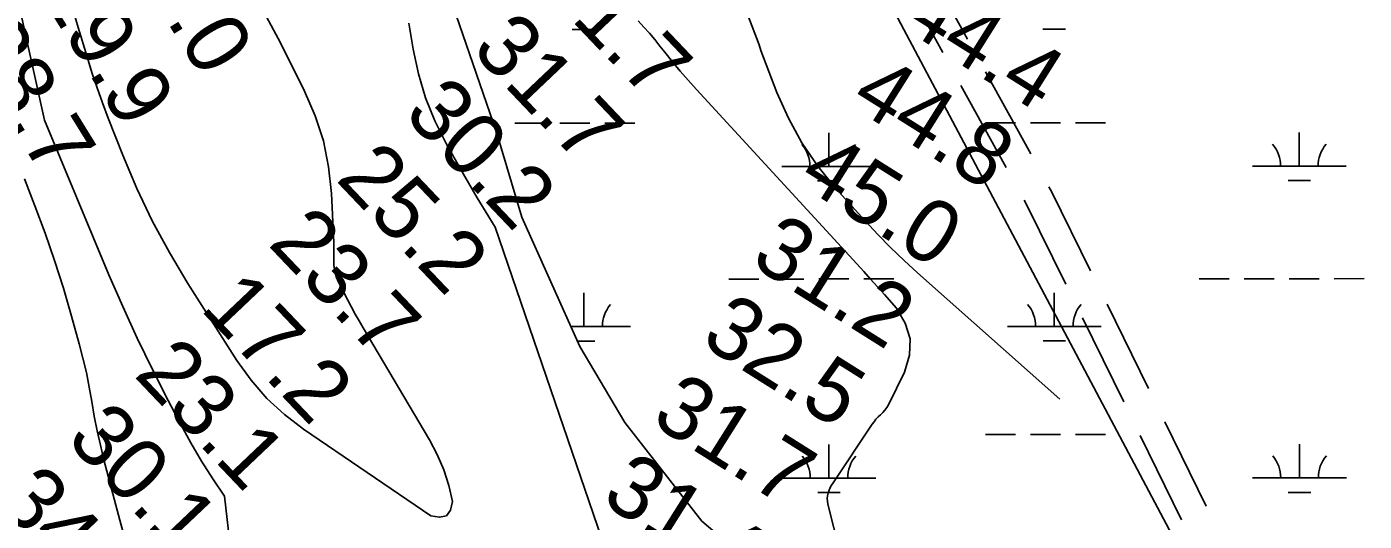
# Model space of a CAD drawing. Extents: x 3279314 to 3317160, y 734079 to 759431.
# Drawn here: x 3288596 to 3290023, y 756091 to 756619 of the extents above; entities that cross this region are included whole.
import ezdxf

# ---------------------------------------------------------------- set-up
doc = ezdxf.new("R2010")
doc.units = 0
for name, color, linetype in [('V-RIVR-RANG', 7, 'Continuous'), ('V-ROAD-CNTR', 7, 'Continuous'), ('V-SITE-VEGE', 7, 'Continuous'), ('V-TOPO-MAJR', 7, 'Continuous'), ('V-TOPO-MINR', 7, 'Continuous'), ('V-TOPO-SHOR', 7, 'Continuous'), ('V-WETL-SWMP', 7, 'Continuous')]:
    doc.layers.add(name, color=color, linetype=linetype)

msp = doc.modelspace()

# ---------------------------------------------------------------- linework, layer by layer
at = {"layer": 'V-ROAD-CNTR'}
for p, q in [((3289551.6, 756693.1), (3289599.8, 756605.5)), ((3289525.3, 756678.6), (3289573.5, 756591)), ((3289619.1, 756570.5), (3289667.3, 756482.9)), ((3289592.8, 756556), (3289641, 756468.4)), ((3289748.6, 756322.3), (3289792.7, 756232.6)), ((3289722.3, 756307.8), (3289766.4, 756218.1)), ((3289810.3, 756196.7), (3289854.5, 756106.9)), ((3289784, 756182.2), (3289828.2, 756092.4))]:
    msp.add_line(p, q, dxfattribs=at)
for points in [[(3289686.6, 756447.8), (3289689.4, 756442.7), (3289730.9, 756358.2)], [(3289660.3, 756433.3), (3289662.8, 756428.8), (3289704.6, 756343.7)]]:
    msp.add_lwpolyline(points, dxfattribs=at)
at = {"layer": 'V-SITE-VEGE'}
for p, q in [((3289388, 756887.4), (3289693.9, 756309.9)), ((3289097.3, 756506), (3289054.6, 756630.8)), ((3289124.5, 756415.2), (3289097.3, 756506)), ((3289186.3, 756277.4), (3289124.5, 756415.2)), ((3289693.9, 756309.9), (3289867.7, 755982.9)), ((3289234.3, 756196.2), (3289186.3, 756277.4)), ((3289316.6, 756090.7), (3289234.3, 756196.2))]:
    msp.add_line(p, q, dxfattribs=at)
at = {"layer": 'V-TOPO-MAJR'}
for p, q in [((3288585.8, 756653.3), (3288615.2, 756518.7)), ((3289008.5, 756594.8), (3289004, 756622.5)), ((3289014.1, 756568.4), (3289008.5, 756594.8)), ((3289021.6, 756542.7), (3289014.1, 756568.4)), ((3289031.8, 756518), (3289021.6, 756542.7)), ((3288615.2, 756518.7), (3288684.1, 756353.7)), ((3289043.8, 756493.8), (3289031.8, 756518)), ((3289058.3, 756468.1), (3289043.8, 756493.8)), ((3289067.5, 756452), (3289058.3, 756468.1)), ((3289076.9, 756436.1), (3289067.5, 756452)), ((3289086.4, 756420.2), (3289076.9, 756436.1)), ((3289096.1, 756404.5), (3289086.4, 756420.2)), ((3289238.2, 755988.5), (3289096.1, 756404.5)), ((3288684.1, 756353.7), (3288698.8, 756319.8)), ((3288698.8, 756319.8), (3288714.2, 756286.1)), ((3288714.2, 756286.1), (3288730.4, 756252.8)), ((3288730.4, 756252.8), (3288747.2, 756219.8)), ((3288747.2, 756219.8), (3288760.8, 756193.9)), ((3288760.8, 756193.9), (3288771.6, 756174.3)), ((3288771.6, 756174.3), (3288782.9, 756155)), ((3288782.9, 756155), (3288794.9, 756136.1)), ((3288794.9, 756136.1), (3288807.5, 756117.6)), ((3288807.5, 756117.6), (3288837.6, 755854.7))]:
    msp.add_line(p, q, dxfattribs=at)
at = {"layer": 'V-TOPO-MINR'}
for p, q in [((3289377.7, 756599.3), (3289100.2, 757319)), ((3289254.7, 756618.3), (3289248.7, 756624.9)), ((3289260.5, 756611.6), (3289254.7, 756618.3)), ((3289266.2, 756604.8), (3289260.5, 756611.6)), ((3289271.8, 756597.9), (3289266.2, 756604.8)), ((3289276.9, 756591.4), (3289271.8, 756597.9)), ((3289379.4, 756593.2), (3289377.7, 756599.3)), ((3289396.5, 756548.4), (3289379.4, 756593.2)), ((3289285.1, 756581.2), (3289276.9, 756591.4)), ((3289293.5, 756571.2), (3289285.1, 756581.2)), ((3289302, 756561.4), (3289293.5, 756571.2)), ((3289310.8, 756551.7), (3289302, 756561.4)), ((3289481.8, 756365.6), (3289310.8, 756551.7)), ((3289408.8, 756520.9), (3289396.5, 756548.4)), ((3289423, 756494.5), (3289408.8, 756520.9)), ((3289440.1, 756469.9), (3289423, 756494.5)), ((3289459, 756446.4), (3289440.1, 756469.9)), ((3289490.5, 756411.4), (3289459, 756446.4)), ((3289504, 756397), (3289490.5, 756411.4)), ((3289517.8, 756382.8), (3289504, 756397)), ((3289532.1, 756369.1), (3289517.8, 756382.8)), ((3289489.2, 756357.5), (3289481.8, 756365.6)), ((3289546.6, 756355.8), (3289532.1, 756369.1)), ((3289496.5, 756349.3), (3289489.2, 756357.5)), ((3289503.8, 756341.1), (3289496.5, 756349.3)), ((3289698.3, 756221), (3289546.6, 756355.8)), ((3289511.1, 756332.9), (3289503.8, 756341.1)), ((3289523.9, 756318.3), (3289511.1, 756332.9)), ((3289533.3, 756302.1), (3289523.9, 756318.3)), ((3289538.6, 756285.5), (3289533.3, 756302.1)), ((3289537.8, 756268), (3289538.6, 756285.5)), ((3289532.7, 756250), (3289537.8, 756268)), ((3289515.4, 756214.9), (3289532.7, 756250)), ((3289507.1, 756204.4), (3289509.6, 756206.7)), ((3289509.6, 756206.7), (3289511.8, 756209.2)), ((3289511.8, 756209.2), (3289513.7, 756212)), ((3289513.7, 756212), (3289515.4, 756214.9)), ((3289456.5, 756131.9), (3289498.1, 756194.3)), ((3289498.1, 756194.3), (3289500.1, 756197)), ((3289500.1, 756197), (3289502.2, 756199.7)), ((3289502.2, 756199.7), (3289504.6, 756202.1)), ((3289504.6, 756202.1), (3289507.1, 756204.4)), ((3289451.3, 756120.9), (3289452.3, 756123.8)), ((3289452.3, 756123.8), (3289453.5, 756126.6)), ((3289453.5, 756126.6), (3289454.9, 756129.3)), ((3289454.9, 756129.3), (3289456.5, 756131.9)), ((3289450.3, 756115), (3289450.6, 756118)), ((3289450.5, 756112.1), (3289450.3, 756115)), ((3289451, 756109.1), (3289450.5, 756112.1)), ((3289450.6, 756118), (3289451.3, 756120.9)), ((3289473, 756021.9), (3289451, 756109.1))]:
    msp.add_line(p, q, dxfattribs=at)
for points in [[(3288643.7, 756643.3), (3288651.1, 756617.9), (3288660.7, 756586.3), (3288665.9, 756569.8), (3288671.4, 756553.5), (3288677.2, 756537.2), (3288683.3, 756521.1), (3288698.8, 756481.4), (3288713.9, 756446.1), (3288730.3, 756411.3), (3288748.6, 756377.6), (3288768.3, 756344.6), (3288820.6, 756262.2), (3288835.8, 756241.3), (3288852.4, 756221.9), (3288871.3, 756204.6), (3288891.7, 756188.9), (3289027.3, 756096.7), (3289036.7, 756095), (3289044, 756096.5)], [(3289044, 756096.5), (3289048.3, 756102.6), (3289050.6, 756111.7), (3289046.5, 756129), (3289041.2, 756145.8), (3289034.2, 756162), (3289026, 756177.7), (3288955.1, 756297.2), (3288950.8, 756304.5), (3288946.7, 756311.8), (3288942.7, 756319.2), (3288938.9, 756326.6), (3288929.1, 756345.9), (3288926.6, 756351.7), (3288924.9, 756357.6), (3288924, 756363.7), (3288923.8, 756370), (3288924, 756376.4), (3288924, 756382.8), (3288923.9, 756389.1), (3288923.7, 756395.5), (3288921.5, 756440.5), (3288918.3, 756468.9), (3288912.8, 756496.7), (3288903.9, 756523.6), (3288892.7, 756549.9), (3288866.9, 756601.3), (3288852.1, 756629.1)], [(3288594.2, 756456.1), (3288605.2, 756427.6), (3288616, 756398.4), (3288626.2, 756369.1), (3288635.5, 756339.5), (3288644.2, 756309.7), (3288652.4, 756280.3), (3288656.4, 756265), (3288660, 756249.6), (3288663.1, 756234), (3288665.8, 756218.4), (3288668.5, 756202.8), (3288671.6, 756187.3), (3288675, 756171.8), (3288678.8, 756156.4), (3288691.5, 756107.9), (3288695.8, 756092), (3288700.1, 756076.2)]]:
    msp.add_lwpolyline(points, dxfattribs=at)
at = {"layer": 'V-TOPO-SHOR'}
msp.add_lwpolyline([(3288745.6, 757365.7), (3288755.2, 757352.5), (3288764.8, 757341.2), (3288784, 757303.5), (3288807.1, 757258.2), (3288834.1, 757203.4), (3288876.4, 757118.4), (3288905.3, 757061.8), (3288949.6, 756976.8), (3288972.8, 756922.1), (3288998, 756848.3), (3289015.4, 756793.5), (3289035.1, 756702.7), (3289054.6, 756630.8), (3289097.3, 756506), (3289124.5, 756415.2), (3289186.3, 756277.4), (3289234.3, 756196.2), (3289316.6, 756090.7)], dxfattribs=at)
at = {"layer": 'V-WETL-SWMP'}
for p, q in [((3289097.3, 756506), (3289054.6, 756630.8)), ((3289097.3, 756506), (3289054.6, 756630.8)), ((3289178.3, 756615.7), (3289202.3, 756615.7)), ((3289680.2, 756616), (3289704.2, 756616)), ((3289117, 756515.7), (3289149, 756515.7)), ((3289165, 756515.7), (3289197, 756515.7)), ((3289213, 756515.7), (3289245, 756515.8)), ((3289618.9, 756515.9), (3289650.9, 756516)), ((3289666.9, 756516), (3289698.9, 756516)), ((3289714.9, 756516), (3289746.9, 756516)), ((3289124.5, 756415.3), (3289097.3, 756506)), ((3289124.5, 756415.3), (3289097.3, 756506)), ((3289451.8, 756469.4), (3289451.8, 756505.4)), ((3289953.7, 756469.7), (3289953.7, 756505.7)), ((3289401.8, 756469.4), (3289501.8, 756469.5)), ((3289903.7, 756469.7), (3290003.7, 756469.7)), ((3289439.8, 756454), (3289463.8, 756454)), ((3289941.8, 756454.3), (3289965.8, 756454.3)), ((3289186.3, 756277.4), (3289124.5, 756415.3)), ((3289186.3, 756277.4), (3289124.5, 756415.3)), ((3289345.1, 756349.3), (3289377.1, 756349.3)), ((3289393.1, 756349.3), (3289425.1, 756349.3)), ((3289441.1, 756349.4), (3289473.1, 756349.4)), ((3289489.1, 756349.4), (3289521.1, 756349.4)), ((3289847, 756349.6), (3289879, 756349.6)), ((3289895, 756349.6), (3289927, 756349.6)), ((3289943, 756349.6), (3289975, 756349.6)), ((3289991, 756349.6), (3290023, 756349.7)), ((3289190.5, 756298.5), (3289190.5, 756334.5)), ((3289692.4, 756298.7), (3289692.4, 756334.7)), ((3289176.8, 756298.5), (3289240.5, 756298.5)), ((3289642.4, 756298.7), (3289742.4, 756298.8)), ((3289183.7, 756283.1), (3289202.5, 756283.1)), ((3289680.4, 756283.3), (3289704.4, 756283.3)), ((3289234.3, 756196.2), (3289186.3, 756277.4)), ((3289234.3, 756196.2), (3289186.3, 756277.4)), ((3289316.6, 756090.7), (3289234.3, 756196.2)), ((3289316.6, 756090.7), (3289234.3, 756196.2)), ((3289244.5, 756183.1), (3289245.1, 756183.1)), ((3289619, 756183.3), (3289651, 756183.3)), ((3289667, 756183.3), (3289699, 756183.3)), ((3289715, 756183.3), (3289747, 756183.3)), ((3289452, 756136.8), (3289452, 756172.8)), ((3289953.9, 756137), (3289953.9, 756173)), ((3289402, 756136.7), (3289502, 756136.8)), ((3289903.9, 756137), (3290003.9, 756137)), ((3289440, 756121.3), (3289464, 756121.3)), ((3289941.9, 756121.6), (3289965.9, 756121.6)), ((3289371.9, 756043.8), (3289316.6, 756090.7)), ((3289371.9, 756043.8), (3289316.6, 756090.7))]:
    msp.add_line(p, q, dxfattribs=at)
for centre, start, end in [((3289396.6, 756469.9), 359.2573, 40.801), ((3289507.1, 756469.9), 139.2573, 180.801), ((3289898.5, 756470.1), 359.2573, 40.801), ((3290009, 756470.2), 139.2573, 180.801), ((3289245.7, 756299), 139.2573, 180.801), ((3289637.2, 756299.2), 359.2573, 40.801), ((3289747.6, 756299.2), 139.2573, 180.801), ((3289396.8, 756137.2), 359.2573, 40.801), ((3289507.3, 756137.3), 139.2573, 180.801), ((3289898.7, 756137.5), 359.2573, 40.801), ((3290009.2, 756137.5), 139.2573, 180.801)]:
    msp.add_arc(centre, 35.2, start, end, dxfattribs=at)

# ---------------------------------------------------------------- texts
at = {"layer": 'V-RIVR-RANG'}
for s, rotation, p in [('19.0', 301.7483, (3288692.5, 756710.1)), ('31.7', 313.5383, (3289141.9, 756662.5)), ('19.9', 301.7483, (3288609, 756655)), ('44.4', 327.8183, (3289525.9, 756620)), ('28.7', 301.7483, (3288524.2, 756602)), ('31.7', 313.5383, (3289069.5, 756593.4)), ('44.8', 327.8183, (3289472.8, 756535.2)), ('30.2', 313.5383, (3288997.2, 756524.4)), ('45.0', 327.8183, (3289417.3, 756452)), ('25.2', 313.5383, (3288924.9, 756455.3)), ('23.7', 313.5383, (3288852.6, 756386.2)), ('31.2', 327.8183, (3289366.7, 756365.7)), ('17.2', 313.5383, (3288780.3, 756317.2)), ('32.5', 327.8183, (3289313.6, 756280.9)), ('23.1', 313.5383, (3288709.6, 756246.4)), ('31.7', 327.8183, (3289260.6, 756196.1)), ('30.1', 313.5383, (3288637.3, 756177.3)), ('31.4', 327.8183, (3289207.5, 756111.4)), ('34.8', 313.5383, (3288563.3, 756110))]:
    msp.add_text(s, height=67, rotation=rotation, dxfattribs=at).set_placement(p)

doc.saveas('drawing.dxf')
